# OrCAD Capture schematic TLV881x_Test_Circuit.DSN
size A; title: TLV8811,TLV8812 425 nA Precision Nanopower Op Amps for; rev: 1.2; note: Datasheet: SNOSD35A  EVM: N/A
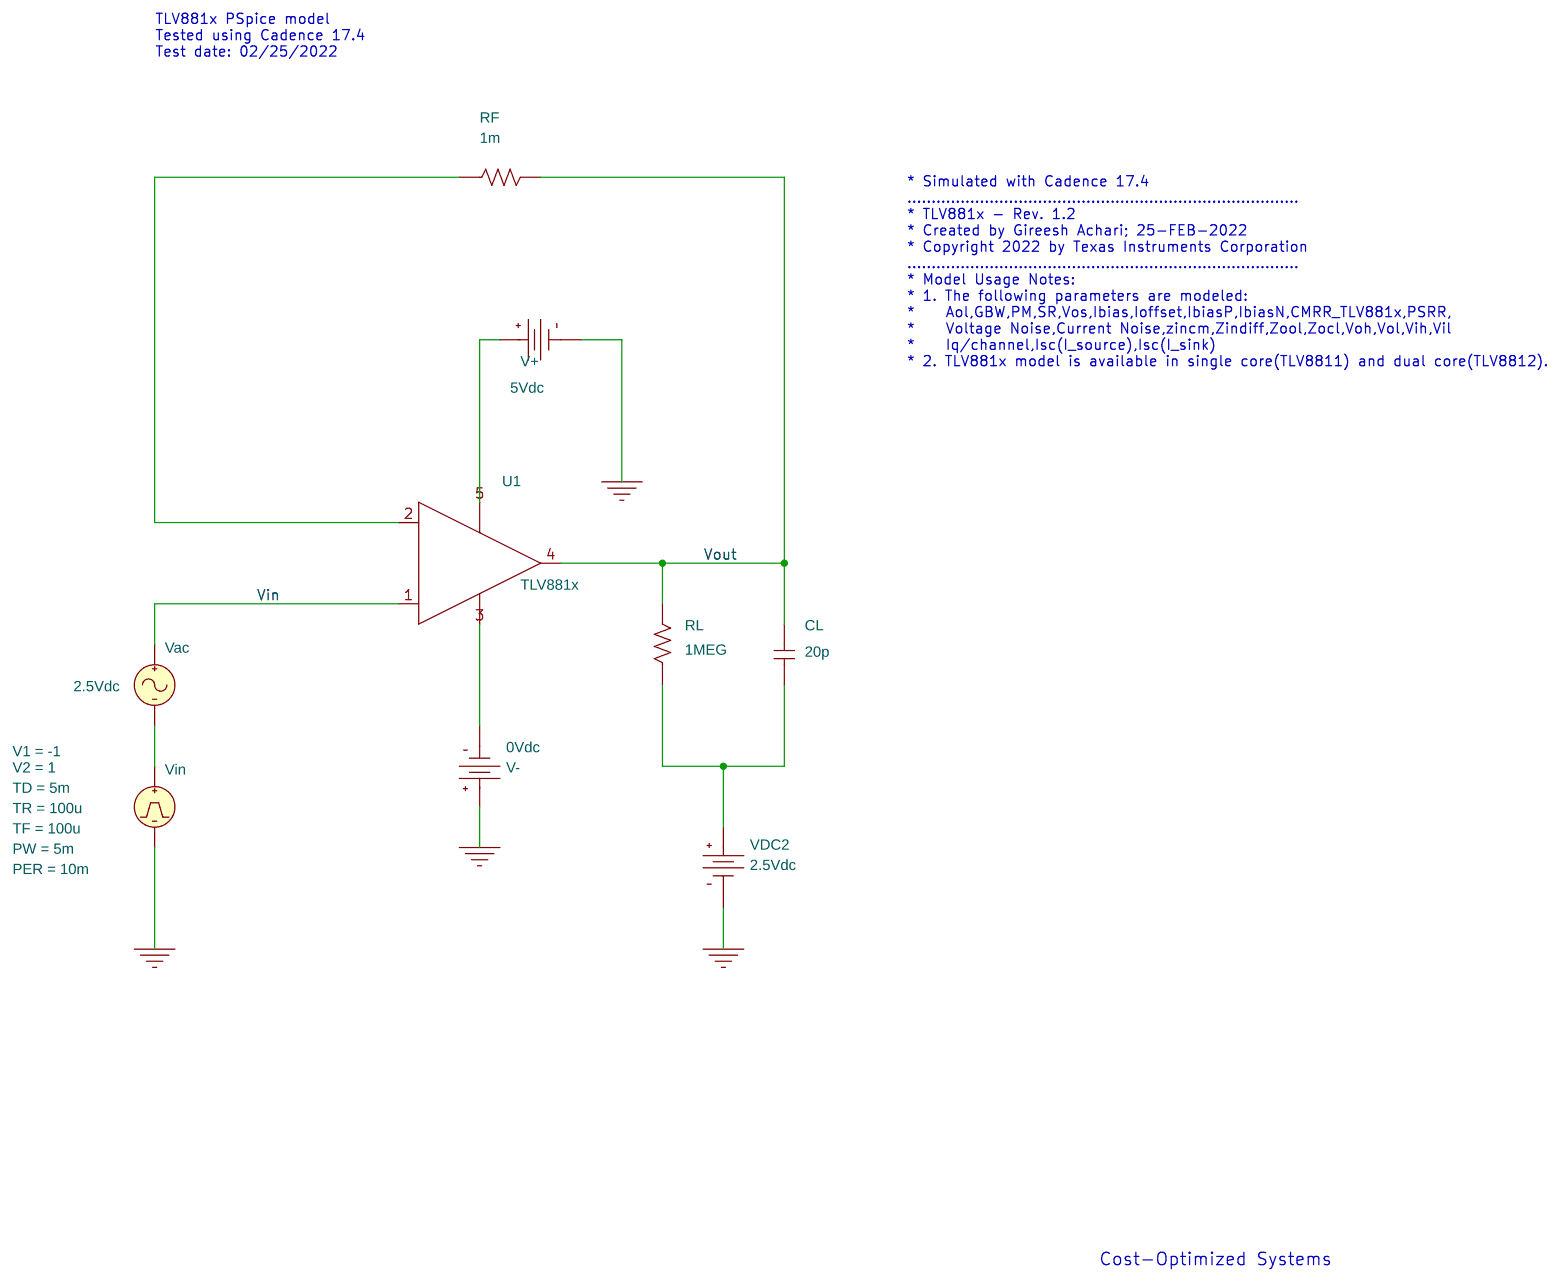
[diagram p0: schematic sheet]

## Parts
CL  20p  [cap196]
RF  1m  [AXRC05]
RL  1MEG  [AXRC05]
U1  TLV881x
V+  VDC
V-  VDC
Vac  VAC
VDC2  VDC
Vin  VPULSE

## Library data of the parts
CL = C
RF RL = R
U1 = TLV881x
V+ = VDC: DC: 5Vdc
V- = VDC: DC: 0Vdc
Vac = VAC: DC: 2.5Vdc
VDC2 = VDC: DC: 2.5Vdc
Vin = VPULSE: PER: 10m; PW: 5m; TD: 5m; TF: 100u; TR: 100u; V1: -1; V2: 1

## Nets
Vin: U1.1(+) Vac.1(+)
0: V+.1(-) V-.0(+) VDC2.1(-) Vin.2(-)
Vout: CL.1 RF.2 RL.2 U1.4(OUT)
N46310: RF.1 U1.2(-)
N46434: U1.5(V+) V+.0(+)
N46592: U1.3(V-) V-.1(-)
N48518: CL.2 RL.1 VDC2.0(+)
N49956: Vac.2(-) Vin.1(+)

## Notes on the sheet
- TLV881x PSpice model
  Tested using Cadence 17.4
  Test date: 02/25/2022
- * Simulated with Cadence 17.4
  .................................................................................
  * TLV881x - Rev. 1.2
  * Created by Gireesh Achari; 25-FEB-2022
  * Copyright 2022 by Texas Instruments Corporation
  .................................................................................
  * Model Usage Notes:
  * 1. The following parameters are modeled:
  *    Aol,GBW,PM,SR,Vos,Ibias,Ioffset,IbiasP,IbiasN,CMRR_TLV881x,PSRR,
  *    Voltage Noise,Current Noise,zincm,Zindiff,Zool,Zocl,Voh,Vol,Vih,Vil
  *    Iq/channel,Isc(I_source),Isc(I_sink)
  * 2. TLV881x model is available in single core(TLV8811) and dual core(TLV8812).
- Cost-Optimized Systems
